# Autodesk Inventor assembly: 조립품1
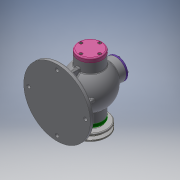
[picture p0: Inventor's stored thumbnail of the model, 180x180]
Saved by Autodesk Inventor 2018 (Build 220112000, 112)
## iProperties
Created: 2020-08
Part Number: 조립품1
Document SubType Name: Assembly
Designer: Administrator
Author: Administrator
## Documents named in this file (17)
- C:\Users\Administrator\Desktop\700806V1054\700806V1054\조립품1.iam
- C:\Users\Administrator\Desktop\700806V1054\700806V1054\부품1.ipt
- C:\Users\Administrator\Desktop\700806V1054\700806V1054\편심축.ipt
- C:\Users\Administrator\Desktop\700806V1054\700806V1054\키 3x3x12.ipt
- C:\Users\Administrator\Desktop\700806V1054\700806V1054\칼라.ipt
- C:\Users\Administrator\Desktop\700806V1054\700806V1054\멈춤링 35x1.6.ipt
- 멈춤링 35x1.6.ipt
- C:\Users\Administrator\Desktop\700806V1054\700806V1054\멈춤링 15x1.ipt
- C:\Users\Administrator\Desktop\700806V1054\700806V1054\베어링 6202.ipt
- 베어링 6202.ipt
- C:\Users\Administrator\Desktop\700806V1054\700806V1054\뒤커버.ipt
- C:\Users\Administrator\Desktop\700806V1054\700806V1054\앞커버.ipt
- C:\Users\Administrator\Desktop\700806V1054\700806V1054\볼트 M4.ipt
- C:\Users\Administrator\Desktop\700806V1054\700806V1054\슬라이드.ipt
- C:\Users\Administrator\Desktop\700806V1054\700806V1054\상부커버.ipt
- C:\Users\Administrator\Desktop\700806V1054\700806V1054\V-벨트풀리.ipt
- C:\Users\Administrator\Desktop\700806V1054\700806V1054\너트 M8.ipt
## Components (1 placed, 1 different names)
1. V-벨트풀리:1
